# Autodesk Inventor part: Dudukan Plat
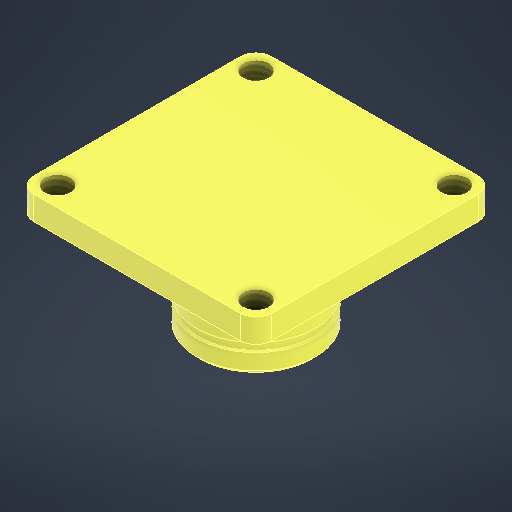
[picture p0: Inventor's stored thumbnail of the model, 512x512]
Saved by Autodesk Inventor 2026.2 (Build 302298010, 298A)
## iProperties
Created: 2021-06
Part Number: Dudukan Plat
Material: Generic
Document SubType Name: Modeling
Designer: ASUS
Density: 1 g/cm^3
Appearance: Smooth - Yellow
Author: ASUS
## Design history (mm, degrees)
sketch "Sketch1"
  geometry: C1 r 7.5 at (0, 0); 1 further point
  constraints: 1 centre point, 1 coincident
  dimensions: "d0" = 15 diameter of C1
extrude "Extrusion1" new body sketch "Sketch1" distance "d1" = 10.5; taper "d2" = 0 deg
sketch "Sketch2"
  geometry: C1 r 11 at (0, 0); 1 further point
  constraints: 1 centre point, 1 coincident
  dimensions: "d3" = 22 diameter of C1
extrude "Extrusion2" join sketch "Sketch2" distance "d4" = 2; taper "d5" = 0 deg
sketch "Sketch3"
  geometry: L1 (-15, -15)-(15, -15); L2 (15, -15)-(15, 15); L3 (15, 15)-(-15, 15); L4 (-15, 15)-(-15, -15); L5 (-15, -15)-(15, 15); L6 (15, -15)-(-15, 15); 1 further point
  constraints: 12 end point, 2 midpoint, 2 parallel, 1 horizontal, 1 perpendicular
  dimensions: "d6" = 30 distance of L3.end L2.end; "d7" = 30 distance of L2.end L1.end
extrude "Extrusion3" join sketch "Sketch3" distance "d8" = 3; taper "d9" = 0 deg
chamfer "Chamfer1" distance "d10" = 0.5; stored, may be unused: second distance "d11" = 2, angle "d12" = 45 deg
workplane "Work Plane1"
sketch "Sketch4"
  geometry: C1 r 7.5 at (0, 0) reference; C2 r 7.15 at (0, 0); 1 further point
  constraints: 1 centre point, 1 coincident
  dimensions: "d14" = 14.3 diameter of C2
extrude "Extrusion4" cut sketch "Sketch4" distance "d15" = 1.1; taper "d16" = 0 deg
sketch "Sketch5"
  geometry: L1 (-12.5, 12.5)-(12.5, 12.5); L2 (12.5, 12.5)-(12.5, -12.5); L3 (12.5, -12.5)-(-12.5, -12.5); L4 (-12.5, -12.5)-(-12.5, 12.5); L5 (-12.5, 12.5)-(12.5, -12.5); L6 (12.5, 12.5)-(-12.5, -12.5); 5 further points
  constraints: 12 end point, 4 coincident, 2 midpoint, 2 parallel, 1 horizontal, 1 perpendicular
  dimensions: "d17" = 25 distance of L2.end L3.end; "d18" = 25 distance of L1.end L2.end
hole "Hole1" sketch "Sketch5" diameter "d19" = 3.242; stored, may be unused: countersink angle "d23" = 90 deg, drill point angle "d25" = 0 deg; dims "d20" = 8, "d21" = 4, "d22" = 2, "d24" = 11.8
fillet "Fillet1" dims "d26" = 2
body "Solid1"
other parameters: "d13" = -13
